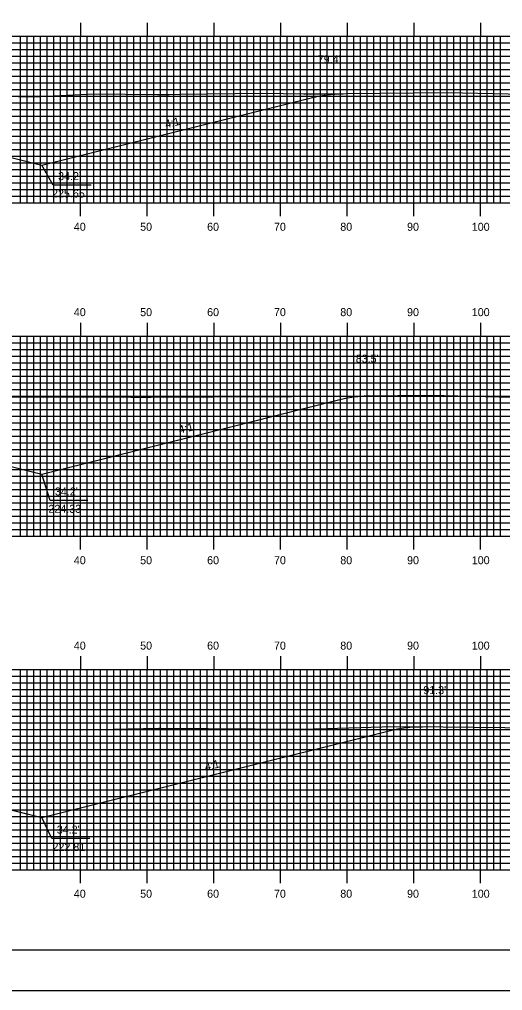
# Model space of a CAD drawing. Extents: x 1802716 to 1803060, y 442591 to 442811.
# Drawn here: x 1802912.9 to 1802985.4, y 442590.5 to 442736.2 of the extents above; entities that cross this region are included whole.
import ezdxf

# ---------------------------------------------------------------- set-up
doc = ezdxf.new("R2010")
doc.units = 0
for name, color, linetype in [('ANNOTATION', 7, 'Continuous'), ('BORDER', 7, 'Continuous'), ('D_Roadway_Centerline', 7, 'Continuous'), ('D_Roadway_SlopeLines', 7, 'Continuous'), ('D_Text_Standard', 7, 'Continuous'), ('H_V ANNOTATION', 7, 'Continuous'), ('MAJOR', 7, 'Continuous'), ('MINOR', 7, 'Continuous'), ('PLOT BOUNDARY', 7, 'Continuous'), ('S_Roadway_Centerline', 7, 'Continuous')]:
    doc.layers.add(name, color=color, linetype=linetype)

msp = doc.modelspace()

# ---------------------------------------------------------------- linework, layer by layer
at = {"layer": 'ANNOTATION'}
for points in [[(1802923.68, 442711.33), (1802917.99, 442711.33), (1802916.29, 442714.31)], [(1802923.21, 442664.05), (1802917.52, 442664.05), (1802916.29, 442668)], [(1802923.49, 442613.35), (1802917.79, 442613.35), (1802916.29, 442616.48)]]:
    msp.add_lwpolyline(points, dxfattribs=at)
at = {"layer": 'BORDER'}
msp.add_lwpolyline([(1802732.51, 442596.67), (1803052.51, 442596.67), (1803052.51, 442806.67), (1802732.51, 442806.67)], close=True, dxfattribs=at)
at = {"layer": 'D_Roadway_Centerline'}
for points in [[(1802803.95, 442724.6), (1802805.2, 442724.6), (1802806.45, 442724.51), (1802807.7, 442724.33), (1802808.95, 442724.06), (1802847.94, 442714.31), (1802851.94, 442715.31), (1802862.11, 442717.85), (1802870.11, 442718.17), (1802882.11, 442718.41), (1802894.11, 442718.17), (1802902.11, 442717.85), (1802912.29, 442715.31), (1802916.29, 442714.31), (1802956.49, 442724.36), (1802957.74, 442724.64), (1802958.99, 442724.84), (1802960.24, 442724.97), (1802961.49, 442725.02)], [(1802798.76, 442679.66), (1802800.01, 442679.63), (1802801.26, 442679.51), (1802802.51, 442679.32), (1802803.76, 442679.04), (1802847.94, 442668), (1802851.94, 442669), (1802862.11, 442671.54), (1802870.11, 442671.86), (1802882.11, 442672.1), (1802894.11, 442671.86), (1802902.11, 442671.54), (1802912.29, 442669), (1802916.29, 442668), (1802960.6, 442679.08), (1802961.85, 442679.35), (1802963.1, 442679.55), (1802964.35, 442679.68), (1802965.6, 442679.72)], [(1802791.35, 442630), (1802792.6, 442629.96), (1802793.85, 442629.84), (1802795.1, 442629.65), (1802796.35, 442629.37), (1802847.94, 442616.48), (1802851.94, 442617.48), (1802862.11, 442620.02), (1802870.11, 442620.34), (1802882.11, 442620.58), (1802894.11, 442620.34), (1802902.11, 442620.02), (1802912.29, 442617.48), (1802916.29, 442616.48), (1802968.41, 442629.51), (1802969.66, 442629.78), (1802970.91, 442629.97), (1802972.16, 442630.08), (1802973.41, 442630.1)]]:
    msp.add_lwpolyline(points, dxfattribs=at)
at = {"layer": 'D_Roadway_SlopeLines'}
for points in [[(1802916.29, 442714.31), (1802956.49, 442724.36), (1802957.74, 442724.64), (1802958.99, 442724.84), (1802960.24, 442724.97), (1802961.49, 442725.02)], [(1802902.11, 442717.85), (1802916.29, 442714.31)], [(1802916.29, 442668), (1802960.6, 442679.08), (1802961.85, 442679.35), (1802963.1, 442679.55), (1802964.35, 442679.68), (1802965.6, 442679.72)], [(1802902.11, 442671.54), (1802916.29, 442668)], [(1802916.29, 442616.48), (1802968.41, 442629.51), (1802969.66, 442629.78), (1802970.91, 442629.97), (1802972.16, 442630.08), (1802973.41, 442630.1)], [(1802902.11, 442620.02), (1802916.29, 442616.48)]]:
    msp.add_lwpolyline(points, dxfattribs=at)
at = {"layer": 'MAJOR'}
for p, q in [((1802922.11, 442735.67), (1802922.11, 442733.67)), ((1802932.11, 442735.67), (1802932.11, 442733.67)), ((1802942.11, 442735.67), (1802942.11, 442733.67)), ((1802952.11, 442735.67), (1802952.11, 442733.67)), ((1802962.11, 442735.67), (1802962.11, 442733.67)), ((1802972.11, 442735.67), (1802972.11, 442733.67)), ((1802982.11, 442735.67), (1802982.11, 442733.67)), ((1802742.11, 442733.67), (1803022.11, 442733.67)), ((1802742.11, 442733.67), (1803022.11, 442733.67)), ((1802922.11, 442708.67), (1802922.11, 442733.67)), ((1802932.11, 442708.67), (1802932.11, 442733.67)), ((1802942.11, 442708.67), (1802942.11, 442733.67)), ((1802952.11, 442708.67), (1802952.11, 442733.67)), ((1802962.11, 442708.67), (1802962.11, 442733.67)), ((1802972.11, 442708.67), (1802972.11, 442733.67)), ((1802982.11, 442708.67), (1802982.11, 442733.67)), ((1802742.11, 442728.67), (1803022.11, 442728.67)), ((1802742.11, 442723.67), (1803022.11, 442723.67)), ((1802742.11, 442718.67), (1803022.11, 442718.67)), ((1802742.11, 442713.67), (1803022.11, 442713.67)), ((1802742.11, 442708.67), (1803022.11, 442708.67)), ((1802742.11, 442708.67), (1803022.11, 442708.67)), ((1802922.11, 442706.66), (1802922.11, 442708.67)), ((1802932.11, 442706.66), (1802932.11, 442708.67)), ((1802942.11, 442706.66), (1802942.11, 442708.67)), ((1802952.11, 442706.66), (1802952.11, 442708.67)), ((1802962.11, 442706.66), (1802962.11, 442708.67)), ((1802972.11, 442706.66), (1802972.11, 442708.67)), ((1802982.11, 442706.66), (1802982.11, 442708.67)), ((1802922.11, 442690.67), (1802922.11, 442688.67)), ((1802932.11, 442690.67), (1802932.11, 442688.67)), ((1802942.11, 442690.67), (1802942.11, 442688.67)), ((1802952.11, 442690.67), (1802952.11, 442688.67)), ((1802962.11, 442690.67), (1802962.11, 442688.67)), ((1802972.11, 442690.67), (1802972.11, 442688.67)), ((1802982.11, 442690.67), (1802982.11, 442688.67)), ((1802742.11, 442688.67), (1803022.11, 442688.67)), ((1802742.11, 442688.67), (1803022.11, 442688.67)), ((1802922.11, 442658.67), (1802922.11, 442688.67)), ((1802932.11, 442658.67), (1802932.11, 442688.67)), ((1802942.11, 442658.67), (1802942.11, 442688.67)), ((1802952.11, 442658.67), (1802952.11, 442688.67)), ((1802962.11, 442658.67), (1802962.11, 442688.67)), ((1802972.11, 442658.67), (1802972.11, 442688.67)), ((1802982.11, 442658.67), (1802982.11, 442688.67)), ((1802742.11, 442683.67), (1803022.11, 442683.67)), ((1802742.11, 442678.67), (1803022.11, 442678.67)), ((1802742.11, 442673.67), (1803022.11, 442673.67)), ((1802742.11, 442668.67), (1803022.11, 442668.67)), ((1802742.11, 442663.67), (1803022.11, 442663.67)), ((1802742.11, 442658.67), (1803022.11, 442658.67)), ((1802742.11, 442658.67), (1803022.11, 442658.67)), ((1802922.11, 442656.66), (1802922.11, 442658.67)), ((1802932.11, 442656.66), (1802932.11, 442658.67)), ((1802942.11, 442656.66), (1802942.11, 442658.67)), ((1802952.11, 442656.66), (1802952.11, 442658.67)), ((1802962.11, 442656.66), (1802962.11, 442658.67)), ((1802972.11, 442656.66), (1802972.11, 442658.67)), ((1802982.11, 442656.66), (1802982.11, 442658.67)), ((1802922.11, 442640.67), (1802922.11, 442638.67)), ((1802932.11, 442640.67), (1802932.11, 442638.67)), ((1802942.11, 442640.67), (1802942.11, 442638.67)), ((1802952.11, 442640.67), (1802952.11, 442638.67)), ((1802962.11, 442640.67), (1802962.11, 442638.67)), ((1802972.11, 442640.67), (1802972.11, 442638.67)), ((1802982.11, 442640.67), (1802982.11, 442638.67)), ((1802742.11, 442638.67), (1803022.11, 442638.67)), ((1802742.11, 442638.67), (1803022.11, 442638.67)), ((1802922.11, 442608.67), (1802922.11, 442638.67)), ((1802932.11, 442608.67), (1802932.11, 442638.67)), ((1802942.11, 442608.67), (1802942.11, 442638.67)), ((1802952.11, 442608.67), (1802952.11, 442638.67)), ((1802962.11, 442608.67), (1802962.11, 442638.67)), ((1802972.11, 442608.67), (1802972.11, 442638.67)), ((1802982.11, 442608.67), (1802982.11, 442638.67)), ((1802742.11, 442633.67), (1803022.11, 442633.67)), ((1802742.11, 442628.67), (1803022.11, 442628.67)), ((1802742.11, 442623.67), (1803022.11, 442623.67)), ((1802742.11, 442618.67), (1803022.11, 442618.67)), ((1802742.11, 442613.67), (1803022.11, 442613.67)), ((1802742.11, 442608.67), (1803022.11, 442608.67)), ((1802742.11, 442608.67), (1803022.11, 442608.67)), ((1802922.11, 442606.66), (1802922.11, 442608.67)), ((1802932.11, 442606.66), (1802932.11, 442608.67)), ((1802942.11, 442606.66), (1802942.11, 442608.67)), ((1802952.11, 442606.66), (1802952.11, 442608.67)), ((1802962.11, 442606.66), (1802962.11, 442608.67)), ((1802972.11, 442606.66), (1802972.11, 442608.67)), ((1802982.11, 442606.66), (1802982.11, 442608.67))]:
    msp.add_line(p, q, dxfattribs=at)
at = {"layer": 'MINOR'}
for p, q in [((1802742.11, 442732.67), (1803022.11, 442732.67)), ((1802913.11, 442708.67), (1802913.11, 442733.67)), ((1802914.11, 442708.67), (1802914.11, 442733.67)), ((1802915.11, 442708.67), (1802915.11, 442733.67)), ((1802916.11, 442708.67), (1802916.11, 442733.67)), ((1802917.11, 442708.67), (1802917.11, 442733.67)), ((1802918.11, 442708.67), (1802918.11, 442733.67)), ((1802919.11, 442708.67), (1802919.11, 442733.67)), ((1802920.11, 442708.67), (1802920.11, 442733.67)), ((1802921.11, 442708.67), (1802921.11, 442733.67)), ((1802923.11, 442708.67), (1802923.11, 442733.67)), ((1802924.11, 442708.67), (1802924.11, 442733.67)), ((1802925.11, 442708.67), (1802925.11, 442733.67)), ((1802926.11, 442708.67), (1802926.11, 442733.67)), ((1802927.11, 442708.67), (1802927.11, 442733.67)), ((1802928.11, 442708.67), (1802928.11, 442733.67)), ((1802929.11, 442708.67), (1802929.11, 442733.67)), ((1802930.11, 442708.67), (1802930.11, 442733.67)), ((1802931.11, 442708.67), (1802931.11, 442733.67)), ((1802933.11, 442708.67), (1802933.11, 442733.67)), ((1802934.11, 442708.67), (1802934.11, 442733.67)), ((1802935.11, 442708.67), (1802935.11, 442733.67)), ((1802936.11, 442708.67), (1802936.11, 442733.67)), ((1802937.11, 442708.67), (1802937.11, 442733.67)), ((1802938.11, 442708.67), (1802938.11, 442733.67)), ((1802939.11, 442708.67), (1802939.11, 442733.67)), ((1802940.11, 442708.67), (1802940.11, 442733.67)), ((1802941.11, 442708.67), (1802941.11, 442733.67)), ((1802943.11, 442708.67), (1802943.11, 442733.67)), ((1802944.11, 442708.67), (1802944.11, 442733.67)), ((1802945.11, 442708.67), (1802945.11, 442733.67)), ((1802946.11, 442708.67), (1802946.11, 442733.67)), ((1802947.11, 442708.67), (1802947.11, 442733.67)), ((1802948.11, 442708.67), (1802948.11, 442733.67)), ((1802949.11, 442708.67), (1802949.11, 442733.67)), ((1802950.11, 442708.67), (1802950.11, 442733.67)), ((1802951.11, 442708.67), (1802951.11, 442733.67)), ((1802953.11, 442708.67), (1802953.11, 442733.67)), ((1802954.11, 442708.67), (1802954.11, 442733.67)), ((1802955.11, 442708.67), (1802955.11, 442733.67)), ((1802956.11, 442708.67), (1802956.11, 442733.67)), ((1802957.11, 442708.67), (1802957.11, 442733.67)), ((1802958.11, 442708.67), (1802958.11, 442733.67)), ((1802959.11, 442708.67), (1802959.11, 442733.67)), ((1802960.11, 442708.67), (1802960.11, 442733.67)), ((1802961.11, 442708.67), (1802961.11, 442733.67)), ((1802963.11, 442708.67), (1802963.11, 442733.67)), ((1802964.11, 442708.67), (1802964.11, 442733.67)), ((1802965.11, 442708.67), (1802965.11, 442733.67)), ((1802966.11, 442708.67), (1802966.11, 442733.67)), ((1802967.11, 442708.67), (1802967.11, 442733.67)), ((1802968.11, 442708.67), (1802968.11, 442733.67)), ((1802969.11, 442708.67), (1802969.11, 442733.67)), ((1802970.11, 442708.67), (1802970.11, 442733.67)), ((1802971.11, 442708.67), (1802971.11, 442733.67)), ((1802973.11, 442708.67), (1802973.11, 442733.67)), ((1802974.11, 442708.67), (1802974.11, 442733.67)), ((1802975.11, 442708.67), (1802975.11, 442733.67)), ((1802976.11, 442708.67), (1802976.11, 442733.67)), ((1802977.11, 442708.67), (1802977.11, 442733.67)), ((1802978.11, 442708.67), (1802978.11, 442733.67)), ((1802979.11, 442708.67), (1802979.11, 442733.67)), ((1802980.11, 442708.67), (1802980.11, 442733.67)), ((1802981.11, 442708.67), (1802981.11, 442733.67)), ((1802983.11, 442708.67), (1802983.11, 442733.67)), ((1802984.11, 442708.67), (1802984.11, 442733.67)), ((1802985.11, 442708.67), (1802985.11, 442733.67)), ((1802742.11, 442731.67), (1803022.11, 442731.67)), ((1802742.11, 442730.67), (1803022.11, 442730.67)), ((1802742.11, 442729.67), (1803022.11, 442729.67)), ((1802742.11, 442727.67), (1803022.11, 442727.67)), ((1802742.11, 442726.67), (1803022.11, 442726.67)), ((1802742.11, 442725.67), (1803022.11, 442725.67)), ((1802742.11, 442724.67), (1803022.11, 442724.67)), ((1802742.11, 442722.67), (1803022.11, 442722.67)), ((1802742.11, 442721.67), (1803022.11, 442721.67)), ((1802742.11, 442720.67), (1803022.11, 442720.67)), ((1802742.11, 442719.67), (1803022.11, 442719.67)), ((1802742.11, 442717.67), (1803022.11, 442717.67)), ((1802742.11, 442716.67), (1803022.11, 442716.67)), ((1802742.11, 442715.67), (1803022.11, 442715.67)), ((1802742.11, 442714.67), (1803022.11, 442714.67)), ((1802742.11, 442712.67), (1803022.11, 442712.67)), ((1802742.11, 442711.67), (1803022.11, 442711.67)), ((1802742.11, 442710.67), (1803022.11, 442710.67)), ((1802742.11, 442709.67), (1803022.11, 442709.67)), ((1802742.11, 442687.67), (1803022.11, 442687.67)), ((1802913.11, 442658.67), (1802913.11, 442688.67)), ((1802914.11, 442658.67), (1802914.11, 442688.67)), ((1802915.11, 442658.67), (1802915.11, 442688.67)), ((1802916.11, 442658.67), (1802916.11, 442688.67)), ((1802917.11, 442658.67), (1802917.11, 442688.67)), ((1802918.11, 442658.67), (1802918.11, 442688.67)), ((1802919.11, 442658.67), (1802919.11, 442688.67)), ((1802920.11, 442658.67), (1802920.11, 442688.67)), ((1802921.11, 442658.67), (1802921.11, 442688.67)), ((1802923.11, 442658.67), (1802923.11, 442688.67)), ((1802924.11, 442658.67), (1802924.11, 442688.67)), ((1802925.11, 442658.67), (1802925.11, 442688.67)), ((1802926.11, 442658.67), (1802926.11, 442688.67)), ((1802927.11, 442658.67), (1802927.11, 442688.67)), ((1802928.11, 442658.67), (1802928.11, 442688.67)), ((1802929.11, 442658.67), (1802929.11, 442688.67)), ((1802930.11, 442658.67), (1802930.11, 442688.67)), ((1802931.11, 442658.67), (1802931.11, 442688.67)), ((1802933.11, 442658.67), (1802933.11, 442688.67)), ((1802934.11, 442658.67), (1802934.11, 442688.67)), ((1802935.11, 442658.67), (1802935.11, 442688.67)), ((1802936.11, 442658.67), (1802936.11, 442688.67)), ((1802937.11, 442658.67), (1802937.11, 442688.67)), ((1802938.11, 442658.67), (1802938.11, 442688.67)), ((1802939.11, 442658.67), (1802939.11, 442688.67)), ((1802940.11, 442658.67), (1802940.11, 442688.67)), ((1802941.11, 442658.67), (1802941.11, 442688.67)), ((1802943.11, 442658.67), (1802943.11, 442688.67)), ((1802944.11, 442658.67), (1802944.11, 442688.67)), ((1802945.11, 442658.67), (1802945.11, 442688.67)), ((1802946.11, 442658.67), (1802946.11, 442688.67)), ((1802947.11, 442658.67), (1802947.11, 442688.67)), ((1802948.11, 442658.67), (1802948.11, 442688.67)), ((1802949.11, 442658.67), (1802949.11, 442688.67)), ((1802950.11, 442658.67), (1802950.11, 442688.67)), ((1802951.11, 442658.67), (1802951.11, 442688.67)), ((1802953.11, 442658.67), (1802953.11, 442688.67)), ((1802954.11, 442658.67), (1802954.11, 442688.67)), ((1802955.11, 442658.67), (1802955.11, 442688.67)), ((1802956.11, 442658.67), (1802956.11, 442688.67)), ((1802957.11, 442658.67), (1802957.11, 442688.67)), ((1802958.11, 442658.67), (1802958.11, 442688.67)), ((1802959.11, 442658.67), (1802959.11, 442688.67)), ((1802960.11, 442658.67), (1802960.11, 442688.67)), ((1802961.11, 442658.67), (1802961.11, 442688.67)), ((1802963.11, 442658.67), (1802963.11, 442688.67)), ((1802964.11, 442658.67), (1802964.11, 442688.67)), ((1802965.11, 442658.67), (1802965.11, 442688.67)), ((1802966.11, 442658.67), (1802966.11, 442688.67)), ((1802967.11, 442658.67), (1802967.11, 442688.67)), ((1802968.11, 442658.67), (1802968.11, 442688.67)), ((1802969.11, 442658.67), (1802969.11, 442688.67)), ((1802970.11, 442658.67), (1802970.11, 442688.67)), ((1802971.11, 442658.67), (1802971.11, 442688.67)), ((1802973.11, 442658.67), (1802973.11, 442688.67)), ((1802974.11, 442658.67), (1802974.11, 442688.67)), ((1802975.11, 442658.67), (1802975.11, 442688.67)), ((1802976.11, 442658.67), (1802976.11, 442688.67)), ((1802977.11, 442658.67), (1802977.11, 442688.67)), ((1802978.11, 442658.67), (1802978.11, 442688.67)), ((1802979.11, 442658.67), (1802979.11, 442688.67)), ((1802980.11, 442658.67), (1802980.11, 442688.67)), ((1802981.11, 442658.67), (1802981.11, 442688.67)), ((1802983.11, 442658.67), (1802983.11, 442688.67)), ((1802984.11, 442658.67), (1802984.11, 442688.67)), ((1802985.11, 442658.67), (1802985.11, 442688.67)), ((1802742.11, 442686.67), (1803022.11, 442686.67)), ((1802742.11, 442685.67), (1803022.11, 442685.67)), ((1802742.11, 442684.67), (1803022.11, 442684.67)), ((1802742.11, 442682.67), (1803022.11, 442682.67)), ((1802742.11, 442681.67), (1803022.11, 442681.67)), ((1802742.11, 442680.67), (1803022.11, 442680.67)), ((1802742.11, 442679.67), (1803022.11, 442679.67)), ((1802742.11, 442677.67), (1803022.11, 442677.67)), ((1802742.11, 442676.67), (1803022.11, 442676.67)), ((1802742.11, 442675.67), (1803022.11, 442675.67)), ((1802742.11, 442674.67), (1803022.11, 442674.67)), ((1802742.11, 442672.67), (1803022.11, 442672.67)), ((1802742.11, 442671.67), (1803022.11, 442671.67)), ((1802742.11, 442670.67), (1803022.11, 442670.67)), ((1802742.11, 442669.67), (1803022.11, 442669.67)), ((1802742.11, 442667.67), (1803022.11, 442667.67)), ((1802742.11, 442666.67), (1803022.11, 442666.67)), ((1802742.11, 442665.67), (1803022.11, 442665.67)), ((1802742.11, 442664.67), (1803022.11, 442664.67)), ((1802742.11, 442662.67), (1803022.11, 442662.67)), ((1802742.11, 442661.67), (1803022.11, 442661.67)), ((1802742.11, 442660.67), (1803022.11, 442660.67)), ((1802742.11, 442659.67), (1803022.11, 442659.67)), ((1802913.11, 442608.67), (1802913.11, 442638.67)), ((1802914.11, 442608.67), (1802914.11, 442638.67)), ((1802915.11, 442608.67), (1802915.11, 442638.67)), ((1802916.11, 442608.67), (1802916.11, 442638.67)), ((1802917.11, 442608.67), (1802917.11, 442638.67)), ((1802918.11, 442608.67), (1802918.11, 442638.67)), ((1802919.11, 442608.67), (1802919.11, 442638.67)), ((1802920.11, 442608.67), (1802920.11, 442638.67)), ((1802921.11, 442608.67), (1802921.11, 442638.67)), ((1802923.11, 442608.67), (1802923.11, 442638.67)), ((1802924.11, 442608.67), (1802924.11, 442638.67)), ((1802925.11, 442608.67), (1802925.11, 442638.67)), ((1802926.11, 442608.67), (1802926.11, 442638.67)), ((1802927.11, 442608.67), (1802927.11, 442638.67)), ((1802928.11, 442608.67), (1802928.11, 442638.67)), ((1802929.11, 442608.67), (1802929.11, 442638.67)), ((1802930.11, 442608.67), (1802930.11, 442638.67)), ((1802931.11, 442608.67), (1802931.11, 442638.67)), ((1802933.11, 442608.67), (1802933.11, 442638.67)), ((1802934.11, 442608.67), (1802934.11, 442638.67)), ((1802935.11, 442608.67), (1802935.11, 442638.67)), ((1802936.11, 442608.67), (1802936.11, 442638.67)), ((1802937.11, 442608.67), (1802937.11, 442638.67)), ((1802938.11, 442608.67), (1802938.11, 442638.67)), ((1802939.11, 442608.67), (1802939.11, 442638.67)), ((1802940.11, 442608.67), (1802940.11, 442638.67)), ((1802941.11, 442608.67), (1802941.11, 442638.67)), ((1802943.11, 442608.67), (1802943.11, 442638.67)), ((1802944.11, 442608.67), (1802944.11, 442638.67)), ((1802945.11, 442608.67), (1802945.11, 442638.67)), ((1802946.11, 442608.67), (1802946.11, 442638.67)), ((1802947.11, 442608.67), (1802947.11, 442638.67)), ((1802948.11, 442608.67), (1802948.11, 442638.67)), ((1802949.11, 442608.67), (1802949.11, 442638.67)), ((1802950.11, 442608.67), (1802950.11, 442638.67)), ((1802951.11, 442608.67), (1802951.11, 442638.67)), ((1802953.11, 442608.67), (1802953.11, 442638.67)), ((1802954.11, 442608.67), (1802954.11, 442638.67)), ((1802955.11, 442608.67), (1802955.11, 442638.67)), ((1802956.11, 442608.67), (1802956.11, 442638.67)), ((1802957.11, 442608.67), (1802957.11, 442638.67)), ((1802958.11, 442608.67), (1802958.11, 442638.67)), ((1802959.11, 442608.67), (1802959.11, 442638.67)), ((1802960.11, 442608.67), (1802960.11, 442638.67)), ((1802961.11, 442608.67), (1802961.11, 442638.67)), ((1802963.11, 442608.67), (1802963.11, 442638.67)), ((1802964.11, 442608.67), (1802964.11, 442638.67)), ((1802965.11, 442608.67), (1802965.11, 442638.67)), ((1802966.11, 442608.67), (1802966.11, 442638.67)), ((1802967.11, 442608.67), (1802967.11, 442638.67)), ((1802968.11, 442608.67), (1802968.11, 442638.67)), ((1802969.11, 442608.67), (1802969.11, 442638.67)), ((1802970.11, 442608.67), (1802970.11, 442638.67)), ((1802971.11, 442608.67), (1802971.11, 442638.67)), ((1802973.11, 442608.67), (1802973.11, 442638.67)), ((1802974.11, 442608.67), (1802974.11, 442638.67)), ((1802975.11, 442608.67), (1802975.11, 442638.67)), ((1802976.11, 442608.67), (1802976.11, 442638.67)), ((1802977.11, 442608.67), (1802977.11, 442638.67)), ((1802978.11, 442608.67), (1802978.11, 442638.67)), ((1802979.11, 442608.67), (1802979.11, 442638.67)), ((1802980.11, 442608.67), (1802980.11, 442638.67)), ((1802981.11, 442608.67), (1802981.11, 442638.67)), ((1802983.11, 442608.67), (1802983.11, 442638.67)), ((1802984.11, 442608.67), (1802984.11, 442638.67)), ((1802985.11, 442608.67), (1802985.11, 442638.67)), ((1802742.11, 442637.67), (1803022.11, 442637.67)), ((1802742.11, 442636.67), (1803022.11, 442636.67)), ((1802742.11, 442635.67), (1803022.11, 442635.67)), ((1802742.11, 442634.67), (1803022.11, 442634.67)), ((1802742.11, 442632.67), (1803022.11, 442632.67)), ((1802742.11, 442631.67), (1803022.11, 442631.67)), ((1802742.11, 442630.67), (1803022.11, 442630.67)), ((1802742.11, 442629.67), (1803022.11, 442629.67)), ((1802742.11, 442627.67), (1803022.11, 442627.67)), ((1802742.11, 442626.67), (1803022.11, 442626.67)), ((1802742.11, 442625.67), (1803022.11, 442625.67)), ((1802742.11, 442624.67), (1803022.11, 442624.67)), ((1802742.11, 442622.67), (1803022.11, 442622.67)), ((1802742.11, 442621.67), (1803022.11, 442621.67)), ((1802742.11, 442620.67), (1803022.11, 442620.67)), ((1802742.11, 442619.67), (1803022.11, 442619.67)), ((1802742.11, 442617.67), (1803022.11, 442617.67)), ((1802742.11, 442616.67), (1803022.11, 442616.67)), ((1802742.11, 442615.67), (1803022.11, 442615.67)), ((1802742.11, 442614.67), (1803022.11, 442614.67)), ((1802742.11, 442612.67), (1803022.11, 442612.67)), ((1802742.11, 442611.67), (1803022.11, 442611.67)), ((1802742.11, 442610.67), (1803022.11, 442610.67)), ((1802742.11, 442609.67), (1803022.11, 442609.67))]:
    msp.add_line(p, q, dxfattribs=at)
at = {"layer": 'PLOT BOUNDARY'}
msp.add_lwpolyline([(1802716.33, 442590.55), (1803056.33, 442590.55), (1803056.33, 442810.55), (1802716.33, 442810.55)], close=True, dxfattribs=at)
at = {"layer": 'S_Roadway_Centerline'}
for points in [[(1802912.77, 442724.61), (1802916.02, 442724.62), (1802924.01, 442725.01), (1802933.66, 442724.89), (1802935.41, 442724.92), (1802937.02, 442724.93), (1802949.42, 442725.08), (1802955.6, 442725), (1802958.79, 442724.98), (1802962.12, 442725.03), (1802977.09, 442725.21), (1802988.55, 442724.96), (1802997.4, 442725.02), (1803012.84, 442725.92), (1803016.56, 442725.93), (1803019.18, 442725.87), (1803022.11, 442725.79)], [(1802911.28, 442679.52), (1802917.62, 442679.58), (1802925.71, 442679.57), (1802929.64, 442679.54), (1802932.71, 442679.52), (1802951.63, 442679.6), (1802952.9, 442679.63), (1802953.84, 442679.63), (1802964.67, 442679.72), (1802974.72, 442679.8), (1802976.64, 442679.76), (1802986.96, 442679.51), (1802997.7, 442679.57), (1802997.9, 442679.57), (1802998.07, 442679.57), (1803009.89, 442679.63), (1803020.47, 442679.14), (1803022.11, 442679.13)], [(1802912.36, 442629.71), (1802922.39, 442629.64), (1802933.82, 442629.87), (1802933.98, 442629.88), (1802934.17, 442629.87), (1802955.33, 442629.75), (1802959.01, 442629.86), (1802969.01, 442630.16), (1802976.45, 442630.07), (1802985.74, 442629.98), (1802997.29, 442629.92), (1803003.78, 442629.83), (1803011.94, 442629.84), (1803015.73, 442629.82), (1803018.95, 442629.8), (1803022.11, 442629.8)]]:
    msp.add_lwpolyline(points, dxfattribs=at)

# ---------------------------------------------------------------- texts
at = {"layer": 'ANNOTATION'}
for p in [(1802934.93, 442719.83), (1802936.98, 442674.03), (1802940.89, 442623.49)]:
    msp.add_text('4:1', height=1.2, rotation=14.0362, dxfattribs=at).set_placement(p)
for s, p in [("34.2'", (1802918.73, 442712.06)), ('225.65', (1802917.82, 442709.46)), ("34.2'", (1802918.25, 442664.78)), ('224.33', (1802917.28, 442662.18)), ("34.2'", (1802918.53, 442614.08)), ('222.81', (1802917.89, 442611.48))]:
    msp.add_text(s, height=1.2, dxfattribs=at).set_placement(p)
at = {"layer": 'D_Text_Standard'}
for s, p in [("79.4'", (1802957.69, 442729.58)), ("83.5'", (1802963.39, 442684.7)), ("91.3'", (1802973.52, 442635))]:
    msp.add_text(s, height=1.2, dxfattribs=at).set_placement(p)
at = {"layer": 'H_V ANNOTATION'}
for s, p in [('40', (1802921.09, 442704.47)), ('50', (1802931.04, 442704.47)), ('60', (1802941.09, 442704.47)), ('70', (1802951.12, 442704.47)), ('80', (1802961.07, 442704.47)), ('90', (1802971.09, 442704.47)), ('100', (1802980.8, 442704.47)), ('40', (1802921.09, 442691.67)), ('50', (1802931.04, 442691.67)), ('60', (1802941.09, 442691.67)), ('70', (1802951.12, 442691.67)), ('80', (1802961.07, 442691.67)), ('90', (1802971.09, 442691.67)), ('100', (1802980.8, 442691.67)), ('40', (1802921.09, 442654.47)), ('50', (1802931.04, 442654.47)), ('60', (1802941.09, 442654.47)), ('70', (1802951.12, 442654.47)), ('80', (1802961.07, 442654.47)), ('90', (1802971.09, 442654.47)), ('100', (1802980.8, 442654.47)), ('40', (1802921.09, 442641.67)), ('50', (1802931.04, 442641.67)), ('60', (1802941.09, 442641.67)), ('70', (1802951.12, 442641.67)), ('80', (1802961.07, 442641.67)), ('90', (1802971.09, 442641.67)), ('100', (1802980.8, 442641.67)), ('40', (1802921.09, 442604.47)), ('50', (1802931.04, 442604.47)), ('60', (1802941.09, 442604.47)), ('70', (1802951.12, 442604.47)), ('80', (1802961.07, 442604.47)), ('90', (1802971.09, 442604.47)), ('100', (1802980.8, 442604.47))]:
    msp.add_text(s, height=1.2, dxfattribs=at).set_placement(p)

doc.saveas('drawing.dxf')
